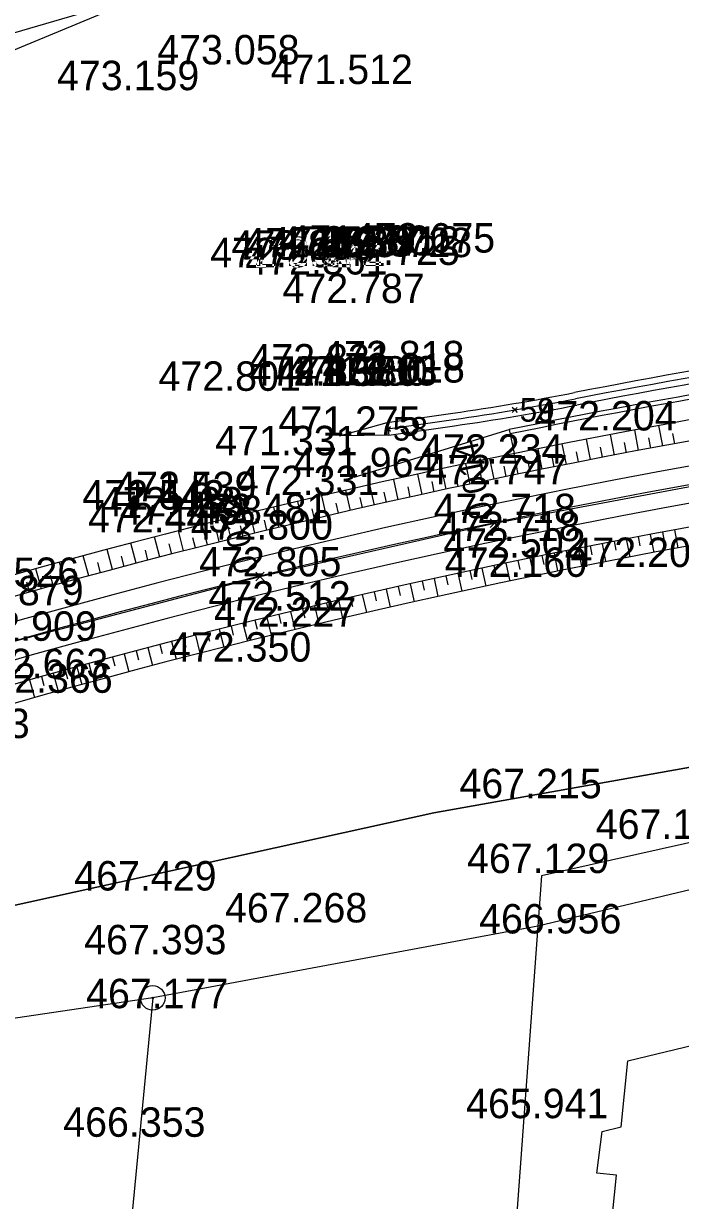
# Model space of a CAD drawing. Extents: x -758836 to -757729, y -1175316 to -1174366.
# Drawn here: x -758284.69 to -758257.91, y -1174798.73 to -1174750.75 of the extents above; entities that cross this region are included whole.
import ezdxf

# ---------------------------------------------------------------- set-up
doc = ezdxf.new("R2010")
doc.units = 0
for name, color, linetype in [('_NOR-body-stávající osa', 7, 'Continuous'), ('_NOR-návrh tenká', 7, 'Continuous'), ('_NOR-osa', 7, 'Continuous'), ('_NOR-posuny', 7, 'Continuous'), ('_NOR-svahy', 7, 'Continuous'), ('_vytyčený bod', 7, 'Continuous'), ('G_Obvod stavby', 7, 'Continuous'), ('Hranice parcel', 7, 'Continuous'), ('Vrstva 1', 7, 'Continuous'), ('Vrstva 61', 7, 'Continuous'), ('Značky bodu BP', 7, 'Continuous')]:
    doc.layers.add(name, color=color, linetype=linetype)

# ---------------------------------------------------------------- blocks, each defined once
blk = doc.blocks.new('POINT_DISPLAY')
for p, q in [((-0.175, -0.175), (0.175, 0.175)), ((-0.175, 0.175), (0.175, -0.175))]:
    blk.add_line(p, q)

msp = doc.modelspace()

# ---------------------------------------------------------------- linework, layer by layer
at = {"layer": '_NOR-návrh tenká'}
for p, q in [((-758271.812, -1174767.556), (-758269.869, -1174767.016)), ((-758271.211, -1174769.241), (-758264.887, -1174767.303)), ((-758269.869, -1174767.016), (-758269.795, -1174767.531)), ((-758264.887, -1174767.303), (-758264.686, -1174768.283)), ((-758269.795, -1174767.531), (-758271.812, -1174767.556))]:
    msp.add_line(p, q, dxfattribs=at)
for points in [[(-758269.869, -1174767.016), (-758267.19, -1174766.633)], [(-758269.832, -1174767.273), (-758267.154, -1174766.89)], [(-758269.795, -1174767.531), (-758267.117, -1174767.148)]]:
    msp.add_lwpolyline(points, dxfattribs=at)
for centre, radius, start, end in [((-758205.34, -1175057.864), 297.557, 97.09744, 101.02201), ((-758205.34, -1175057.864), 297.297, 97.09748, 101.02201), ((-758205.34, -1175057.864), 297.037, 97.09752, 101.02201), ((-758205.34, -1175057.864), 296.6, 97.64234, 101.58164), ((-758205.34, -1175057.864), 296.42, 97.64296, 101.58164), ((-758205.34, -1175057.864), 295.6, 97.09776, 129.28488), ((-758205.34, -1175057.864), 294.75, 97.0979, 129.28474), ((-758281.298, -1174667.896), 99.74, 278.13115, 281.02201), ((-758281.298, -1174667.896), 100, 278.13115, 281.02201), ((-758281.298, -1174667.896), 100.26, 278.13115, 281.02201), ((-758205.34, -1175057.864), 293.75, 97.09807, 120.96729), ((-758205.34, -1175057.864), 292.25, 97.09832, 120.96729), ((-758205.34, -1175057.864), 291.3, 97.09848, 129.28417), ((-758205.34, -1175057.864), 290.55, 97.09861, 129.28404)]:
    msp.add_arc(centre, radius, start, end, dxfattribs=at)
at = {"layer": '_NOR-osa'}
msp.add_arc((-758205.34, -1175057.864), 293, 97.09819, 129.28445, dxfattribs=at)
at = {"layer": '_NOR-svahy'}
for points in [[(-758259.613, -1174768.154), (-758259.769, -1174767.318)], [(-758258.63, -1174767.971), (-758258.783, -1174767.135)], [(-758261.577, -1174768.529), (-758261.74, -1174767.694)], [(-758260.595, -1174768.34), (-758260.755, -1174767.505)], [(-758259.121, -1174768.062), (-758259.199, -1174767.644)], [(-758258.138, -1174767.881), (-758258.214, -1174767.463)], [(-758263.539, -1174768.917), (-758263.707, -1174768.084)], [(-758262.559, -1174768.721), (-758262.724, -1174767.887)], [(-758262.068, -1174768.625), (-758262.15, -1174768.208)], [(-758261.087, -1174768.434), (-758261.167, -1174768.017)], [(-758260.104, -1174768.246), (-758260.183, -1174767.829)], [(-758266.477, -1174769.524), (-758266.654, -1174768.693)], [(-758265.499, -1174769.319), (-758265.672, -1174768.487)], [(-758264.519, -1174769.116), (-758264.69, -1174768.284)], [(-758264.029, -1174769.016), (-758264.114, -1174768.6)], [(-758263.049, -1174768.819), (-758263.132, -1174768.402)], [(-758268.432, -1174769.946), (-758268.614, -1174769.116)], [(-758267.455, -1174769.733), (-758267.634, -1174768.903)], [(-758266.966, -1174769.629), (-758267.055, -1174769.213)], [(-758265.988, -1174769.421), (-758266.075, -1174769.005)], [(-758265.009, -1174769.217), (-758265.095, -1174768.801)], [(-758270.385, -1174770.381), (-758270.572, -1174769.552)], [(-758269.409, -1174770.162), (-758269.594, -1174769.332)], [(-758268.921, -1174770.053), (-758269.012, -1174769.638)], [(-758267.944, -1174769.839), (-758268.034, -1174769.424)], [(-758272.334, -1174770.829), (-758272.527, -1174770.001)], [(-758271.359, -1174770.603), (-758271.55, -1174769.775)], [(-758270.872, -1174770.491), (-758270.967, -1174770.077)], [(-758269.897, -1174770.271), (-758269.99, -1174769.856)], [(-758274.28, -1174771.29), (-758274.479, -1174770.463)], [(-758273.307, -1174771.058), (-758273.503, -1174770.23)], [(-758272.821, -1174770.943), (-758272.918, -1174770.529)], [(-758271.847, -1174770.715), (-758271.943, -1174770.301)], [(-758276.223, -1174771.764), (-758276.427, -1174770.939)], [(-758275.252, -1174771.525), (-758275.453, -1174770.7)], [(-758274.766, -1174771.407), (-758274.866, -1174770.994)], [(-758273.794, -1174771.173), (-758273.892, -1174770.76)], [(-758278.162, -1174772.252), (-758278.372, -1174771.428)], [(-758277.193, -1174772.006), (-758277.4, -1174771.182)], [(-758276.708, -1174771.885), (-758276.811, -1174771.472)], [(-758275.737, -1174771.644), (-758275.839, -1174771.232)], [(-758259.136, -1174771.575), (-758258.997, -1174772.312)], [(-758258.644, -1174771.483), (-758258.576, -1174771.851)], [(-758258.153, -1174771.392), (-758258.017, -1174772.129)], [(-758280.099, -1174772.752), (-758280.314, -1174771.93)], [(-758279.131, -1174772.5), (-758279.344, -1174771.677)], [(-758278.647, -1174772.376), (-758278.752, -1174771.964)], [(-758277.678, -1174772.129), (-758277.782, -1174771.717)], [(-758261.591, -1174772.047), (-758261.518, -1174772.415)], [(-758261.1, -1174771.951), (-758260.957, -1174772.687)], [(-758260.609, -1174771.855), (-758260.538, -1174772.224)], [(-758260.118, -1174771.761), (-758259.977, -1174772.498)], [(-758259.627, -1174771.667), (-758259.557, -1174772.036)], [(-758282.032, -1174773.266), (-758282.253, -1174772.446)], [(-758281.066, -1174773.008), (-758281.284, -1174772.186)], [(-758280.582, -1174772.88), (-758280.691, -1174772.469)], [(-758279.615, -1174772.626), (-758279.722, -1174772.215)], [(-758264.042, -1174772.54), (-758263.891, -1174773.275)], [(-758263.552, -1174772.44), (-758263.477, -1174772.807)], [(-758263.062, -1174772.34), (-758262.913, -1174773.075)], [(-758262.572, -1174772.242), (-758262.498, -1174772.609)], [(-758262.081, -1174772.144), (-758261.935, -1174772.879)], [(-758283.961, -1174773.793), (-758284.188, -1174772.974)], [(-758282.997, -1174773.528), (-758283.221, -1174772.708)], [(-758282.514, -1174773.397), (-758282.625, -1174772.987)], [(-758281.549, -1174773.137), (-758281.659, -1174772.726)], [(-758266.488, -1174773.054), (-758266.41, -1174773.421)], [(-758265.999, -1174772.95), (-758265.843, -1174773.683)], [(-758265.51, -1174772.846), (-758265.433, -1174773.213)], [(-758265.021, -1174772.743), (-758264.867, -1174773.477)], [(-758264.531, -1174772.641), (-758264.455, -1174773.008)], [(-758284.443, -1174773.927), (-758284.557, -1174773.518)], [(-758283.479, -1174773.66), (-758283.592, -1174773.25)], [(-758268.442, -1174773.481), (-758268.361, -1174773.847)], [(-758267.954, -1174773.373), (-758267.793, -1174774.106)], [(-758267.466, -1174773.266), (-758267.386, -1174773.632)], [(-758266.977, -1174773.16), (-758266.818, -1174773.893)], [(-758270.88, -1174774.033), (-758270.712, -1174774.764)], [(-758270.393, -1174773.921), (-758270.309, -1174774.286)], [(-758269.906, -1174773.81), (-758269.74, -1174774.541)], [(-758269.418, -1174773.699), (-758269.336, -1174774.065)], [(-758268.93, -1174773.59), (-758268.767, -1174774.322)], [(-758272.828, -1174774.49), (-758272.654, -1174775.219)], [(-758272.341, -1174774.374), (-758272.255, -1174774.739)], [(-758271.854, -1174774.26), (-758271.683, -1174774.99)], [(-758271.368, -1174774.146), (-758271.283, -1174774.511)], [(-758274.772, -1174774.96), (-758274.593, -1174775.688)], [(-758274.286, -1174774.841), (-758274.197, -1174775.205)], [(-758273.8, -1174774.723), (-758273.624, -1174775.452)], [(-758273.314, -1174774.606), (-758273.226, -1174774.971)], [(-758276.712, -1174775.443), (-758276.529, -1174776.17)], [(-758276.227, -1174775.321), (-758276.136, -1174775.685)], [(-758275.742, -1174775.2), (-758275.561, -1174775.927)], [(-758275.257, -1174775.079), (-758275.167, -1174775.443)], [(-758278.65, -1174775.94), (-758278.461, -1174776.666)], [(-758278.166, -1174775.814), (-758278.072, -1174776.177)], [(-758277.681, -1174775.69), (-758277.495, -1174776.416)], [(-758277.197, -1174775.566), (-758277.104, -1174775.929)], [(-758280.1, -1174776.321), (-758280.004, -1174776.683)], [(-758279.617, -1174776.193), (-758279.426, -1174776.918)], [(-758279.133, -1174776.066), (-758279.038, -1174776.429)], [(-758282.032, -1174776.841), (-758281.933, -1174777.203)], [(-758281.549, -1174776.71), (-758281.353, -1174777.434)], [(-758281.066, -1174776.579), (-758280.969, -1174776.941)], [(-758280.584, -1174776.45), (-758280.39, -1174777.174)], [(-758283.959, -1174777.374), (-758283.858, -1174777.735)], [(-758283.478, -1174777.24), (-758283.277, -1174777.962)], [(-758282.996, -1174777.106), (-758282.896, -1174777.467)], [(-758282.514, -1174776.973), (-758282.315, -1174777.696)], [(-758284.441, -1174777.509), (-758284.237, -1174778.231)]]:
    msp.add_lwpolyline(points, dxfattribs=at)
at = {"layer": '_vytyčený bod'}
for p, q in [((-758264.661, -1174766.502), (-758264.761, -1174766.402)), ((-758264.661, -1174766.502), (-758264.761, -1174766.602)), ((-758264.661, -1174766.502), (-758264.561, -1174766.402)), ((-758264.661, -1174766.502), (-758264.561, -1174766.602)), ((-758269.832, -1174767.273), (-758269.932, -1174767.173)), ((-758269.832, -1174767.273), (-758269.932, -1174767.373)), ((-758269.832, -1174767.273), (-758269.732, -1174767.173)), ((-758269.832, -1174767.273), (-758269.732, -1174767.373))]:
    msp.add_line(p, q, dxfattribs=at)
at = {"layer": 'G_Obvod stavby'}
msp.add_lwpolyline([(-758392.72, -1174840.756), (-758391.23, -1174838.56), (-758368.37, -1174821.64), (-758340.31, -1174807.33), (-758320.27, -1174796.89), (-758301, -1174790.21), (-758267.96, -1174782.93), (-758224.96, -1174775.27), (-758184.87, -1174772.83), (-758142.71, -1174770.26), (-758089.84, -1174768.68), (-758106.02, -1174731.44), (-758149.09, -1174725.67), (-758199.62, -1174726.6), (-758225.76, -1174732.36), (-758252.17, -1174738.18), (-758254.97, -1174739.34), (-758266.58, -1174744.16), (-758279.45, -1174749.49), (-758302.42, -1174759.02), (-758331.68, -1174770.24), (-758367.17, -1174799.81), (-758405.64, -1174832.2)], dxfattribs=at)
at = {"layer": 'Hranice parcel'}
for p, q in [((-758279.45, -1174749.49), (-758305.02, -1174756.99)), ((-758225.62, -1174776.96), (-758263.57, -1174785.5)), ((-758238.83, -1174781.6), (-758263.72, -1174787.54)), ((-758263.57, -1174785.5), (-758263.72, -1174787.54)), ((-758263.72, -1174787.54), (-758279.42, -1174790.47)), ((-758263.72, -1174787.54), (-758266.21, -1174821.26)), ((-758279.42, -1174790.47), (-758292.27, -1174792.38))]:
    msp.add_line(p, q, dxfattribs=at)
for points in [[(-758279.45, -1174749.49), (-758302.42, -1174759.02), (-758331.68, -1174770.24)], [(-758184.87, -1174772.83), (-758224.96, -1174775.27), (-758267.96, -1174782.93), (-758301, -1174790.21), (-758320.27, -1174796.89)], [(-758279.42, -1174790.47), (-758280.36, -1174800.21), (-758281.37, -1174809.16), (-758283.71, -1174840.27)], [(-758261.31, -1174797.61), (-758261.1, -1174795.92), (-758260.32, -1174795.73), (-758260.05, -1174793.03), (-758249.97, -1174790.6), (-758245.99, -1174807.02), (-758245.12, -1174810.68), (-758252.37, -1174812.37), (-758253.43, -1174807.62), (-758255.84, -1174806.71), (-758258.27, -1174805.48), (-758261.38, -1174806.26), (-758260.52, -1174797.7), (-758261.31, -1174797.61)]]:
    msp.add_lwpolyline(points, dxfattribs=at)
at = {"layer": 'Vrstva 1'}
for points in [[(-758275.047, -1174773.289), (-758265.484, -1174771.118), (-758253.61, -1174768.888), (-758243.69, -1174767.426), (-758231.371, -1174766.042), (-758219.363, -1174765.122), (-758206.915, -1174764.505), (-758194.225, -1174764.118), (-758182.013, -1174763.871), (-758170.862, -1174763.683), (-758162.019, -1174763.496), (-758153.195, -1174763.228), (-758152.069, -1174763.19), (-758141.836, -1174762.716), (-758130.402, -1174761.933), (-758120.726, -1174760.981), (-758108.612, -1174759.398), (-758096.467, -1174757.277), (-758085.591, -1174754.917)], [(-758443.817, -1174881.252), (-758441.673, -1174879.1), (-758423.412, -1174860.854), (-758412.446, -1174850.23), (-758405.322, -1174843.614), (-758399.028, -1174837.996), (-758392.64, -1174832.554), (-758380.106, -1174822.693), (-758371.773, -1174816.721), (-758363.37, -1174811.125), (-758354.46, -1174805.649), (-758345.526, -1174800.592), (-758336.614, -1174795.909), (-758327.338, -1174791.462), (-758317.813, -1174787.314), (-758307.666, -1174783.315), (-758298.059, -1174779.921), (-758285.017, -1174775.914), (-758275.047, -1174773.289)]]:
    msp.add_lwpolyline(points, dxfattribs=at)
at = {"layer": 'Značky bodu BP'}
for radius in [0.5, 0.0303]:
    msp.add_circle((-758279.42, -1174790.47), radius, dxfattribs=at)

# ---------------------------------------------------------------- block references
at = {"layer": '_NOR-body-stávající osa'}
for p in [(-758265.484, -1174771.118), (-758275.047, -1174773.289)]:
    msp.add_blockref('POINT_DISPLAY', p, dxfattribs=at)

# ---------------------------------------------------------------- texts
at = {"layer": '_NOR-posuny'}
for s, rotation, p in [('0,014', 101.8459, (-758265.538, -1174770.859)), ('0,012', 103.7637, (-758275.109, -1174773.035))]:
    msp.add_text(s, height=0.9599, rotation=rotation, dxfattribs=at).set_placement(p)
at = {"layer": '_vytyčený bod'}
for s, height, p in [('59', 0.9599, (-758264.461, -1174766.982)), ('59', 0.9596, (-758264.461, -1174766.982)), ('58', 0.9599, (-758269.632, -1174767.753)), ('58', 0.9596, (-758269.632, -1174767.753))]:
    msp.add_text(s, height=height, dxfattribs=at).set_placement(p)
at = {"layer": 'Vrstva 61'}
for s, p in [('473.058', (-758279.236, -1174752.418)), ('473.159', (-758283.325, -1174753.468)), ('471.512', (-758274.615, -1174753.218)), ('473.863', (-758276.214, -1174760.379)), ('472.835', (-758275.727, -1174760.286)), ('472.035', (-758275.727, -1174760.287)), ('471.638', (-758274.717, -1174760.248)), ('471.237', (-758274.274, -1174760.212)), ('472.037', (-758274.273, -1174760.212)), ('471.580', (-758273.919, -1174760.183)), ('472.712', (-758272.707, -1174760.219)), ('471.912', (-758272.704, -1174760.22)), ('473.728', (-758272.203, -1174760.274)), ('472.675', (-758271.264, -1174760.089)), ('472.862', (-758277.077, -1174760.687)), ('472.842', (-758275.731, -1174760.64)), ('472.725', (-758272.705, -1174760.593)), ('472.861', (-758275.648, -1174760.982)), ('472.787', (-758274.132, -1174762.146)), ('472.831', (-758275.479, -1174765.018)), ('472.818', (-758272.517, -1174764.887)), ('472.831', (-758275.479, -1174765.518)), ('472.131', (-758275.478, -1174765.518)), ('471.580', (-758274.387, -1174765.521)), ('471.980', (-758274.006, -1174765.513)), ('471.180', (-758274.006, -1174765.514)), ('471.713', (-758273.609, -1174765.506)), ('472.018', (-758272.501, -1174765.387)), ('472.818', (-758272.495, -1174765.386)), ('472.801', (-758279.186, -1174765.724)), ('472.801', (-758279.186, -1174765.724)), ('471.275', (-758274.297, -1174767.556)), ('472.204', (-758263.862, -1174767.34)), ('471.331', (-758276.872, -1174768.351)), ('471.331', (-758276.872, -1174768.351)), ('472.234', (-758268.479, -1174768.695)), ('471.964', (-758273.696, -1174769.241)), ('472.747', (-758268.309, -1174769.536)), ('471.539', (-758280.993, -1174770.222)), ('472.439', (-758280.989, -1174770.221)), ('472.331', (-758275.983, -1174769.977)), ('472.331', (-758275.983, -1174769.977)), ('471.542', (-758282.293, -1174770.565)), ('472.442', (-758282.284, -1174770.563)), ('472.438', (-758281.543, -1174770.846)), ('472.438', (-758280.768, -1174771.181)), ('472.481', (-758278.059, -1174771.119)), ('472.481', (-758278.059, -1174771.119)), ('472.718', (-758267.969, -1174771.118)), ('472.445', (-758282.059, -1174771.495)), ('472.800', (-758277.877, -1174771.793)), ('472.800', (-758277.877, -1174771.793)), ('472.718', (-758267.785, -1174771.85)), ('472.502', (-758267.574, -1174772.526)), ('472.805', (-758277.532, -1174773.289)), ('472.805', (-758277.532, -1174773.289)), ('472.160', (-758267.516, -1174773.308)), ('472.203', (-758262.389, -1174772.905)), ('472.526', (-758288.221, -1174773.719)), ('472.879', (-758288.038, -1174774.467)), ('472.512', (-758277.152, -1174774.682)), ('472.512', (-758277.152, -1174774.682)), ('472.227', (-758276.923, -1174775.339)), ('472.227', (-758276.923, -1174775.339)), ('472.909', (-758287.502, -1174775.914)), ('472.350', (-758278.756, -1174776.763)), ('472.350', (-758278.756, -1174776.763)), ('472.663', (-758287.032, -1174777.438)), ('472.366', (-758286.853, -1174778.034)), ('472.473', (-758290.238, -1174779.88)), ('467.215', (-758266.917, -1174782.332)), ('467.215', (-758266.917, -1174782.332)), ('467.127', (-758261.358, -1174783.988)), ('467.129', (-758266.61, -1174785.382)), ('467.129', (-758266.61, -1174785.382)), ('467.429', (-758282.62, -1174786.093)), ('467.268', (-758276.476, -1174787.395)), ('466.956', (-758266.117, -1174787.844)), ('466.956', (-758266.117, -1174787.844)), ('467.393', (-758282.216, -1174788.694)), ('467.177', (-758282.138, -1174790.891)), ('465.941', (-758266.645, -1174795.374)), ('465.941', (-758266.645, -1174795.374)), ('466.353', (-758283.07, -1174796.133))]:
    msp.add_text(s, height=1.2, dxfattribs=at).set_placement(p)

doc.saveas('drawing.dxf')
